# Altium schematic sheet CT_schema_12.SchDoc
size 742 x 377 mm
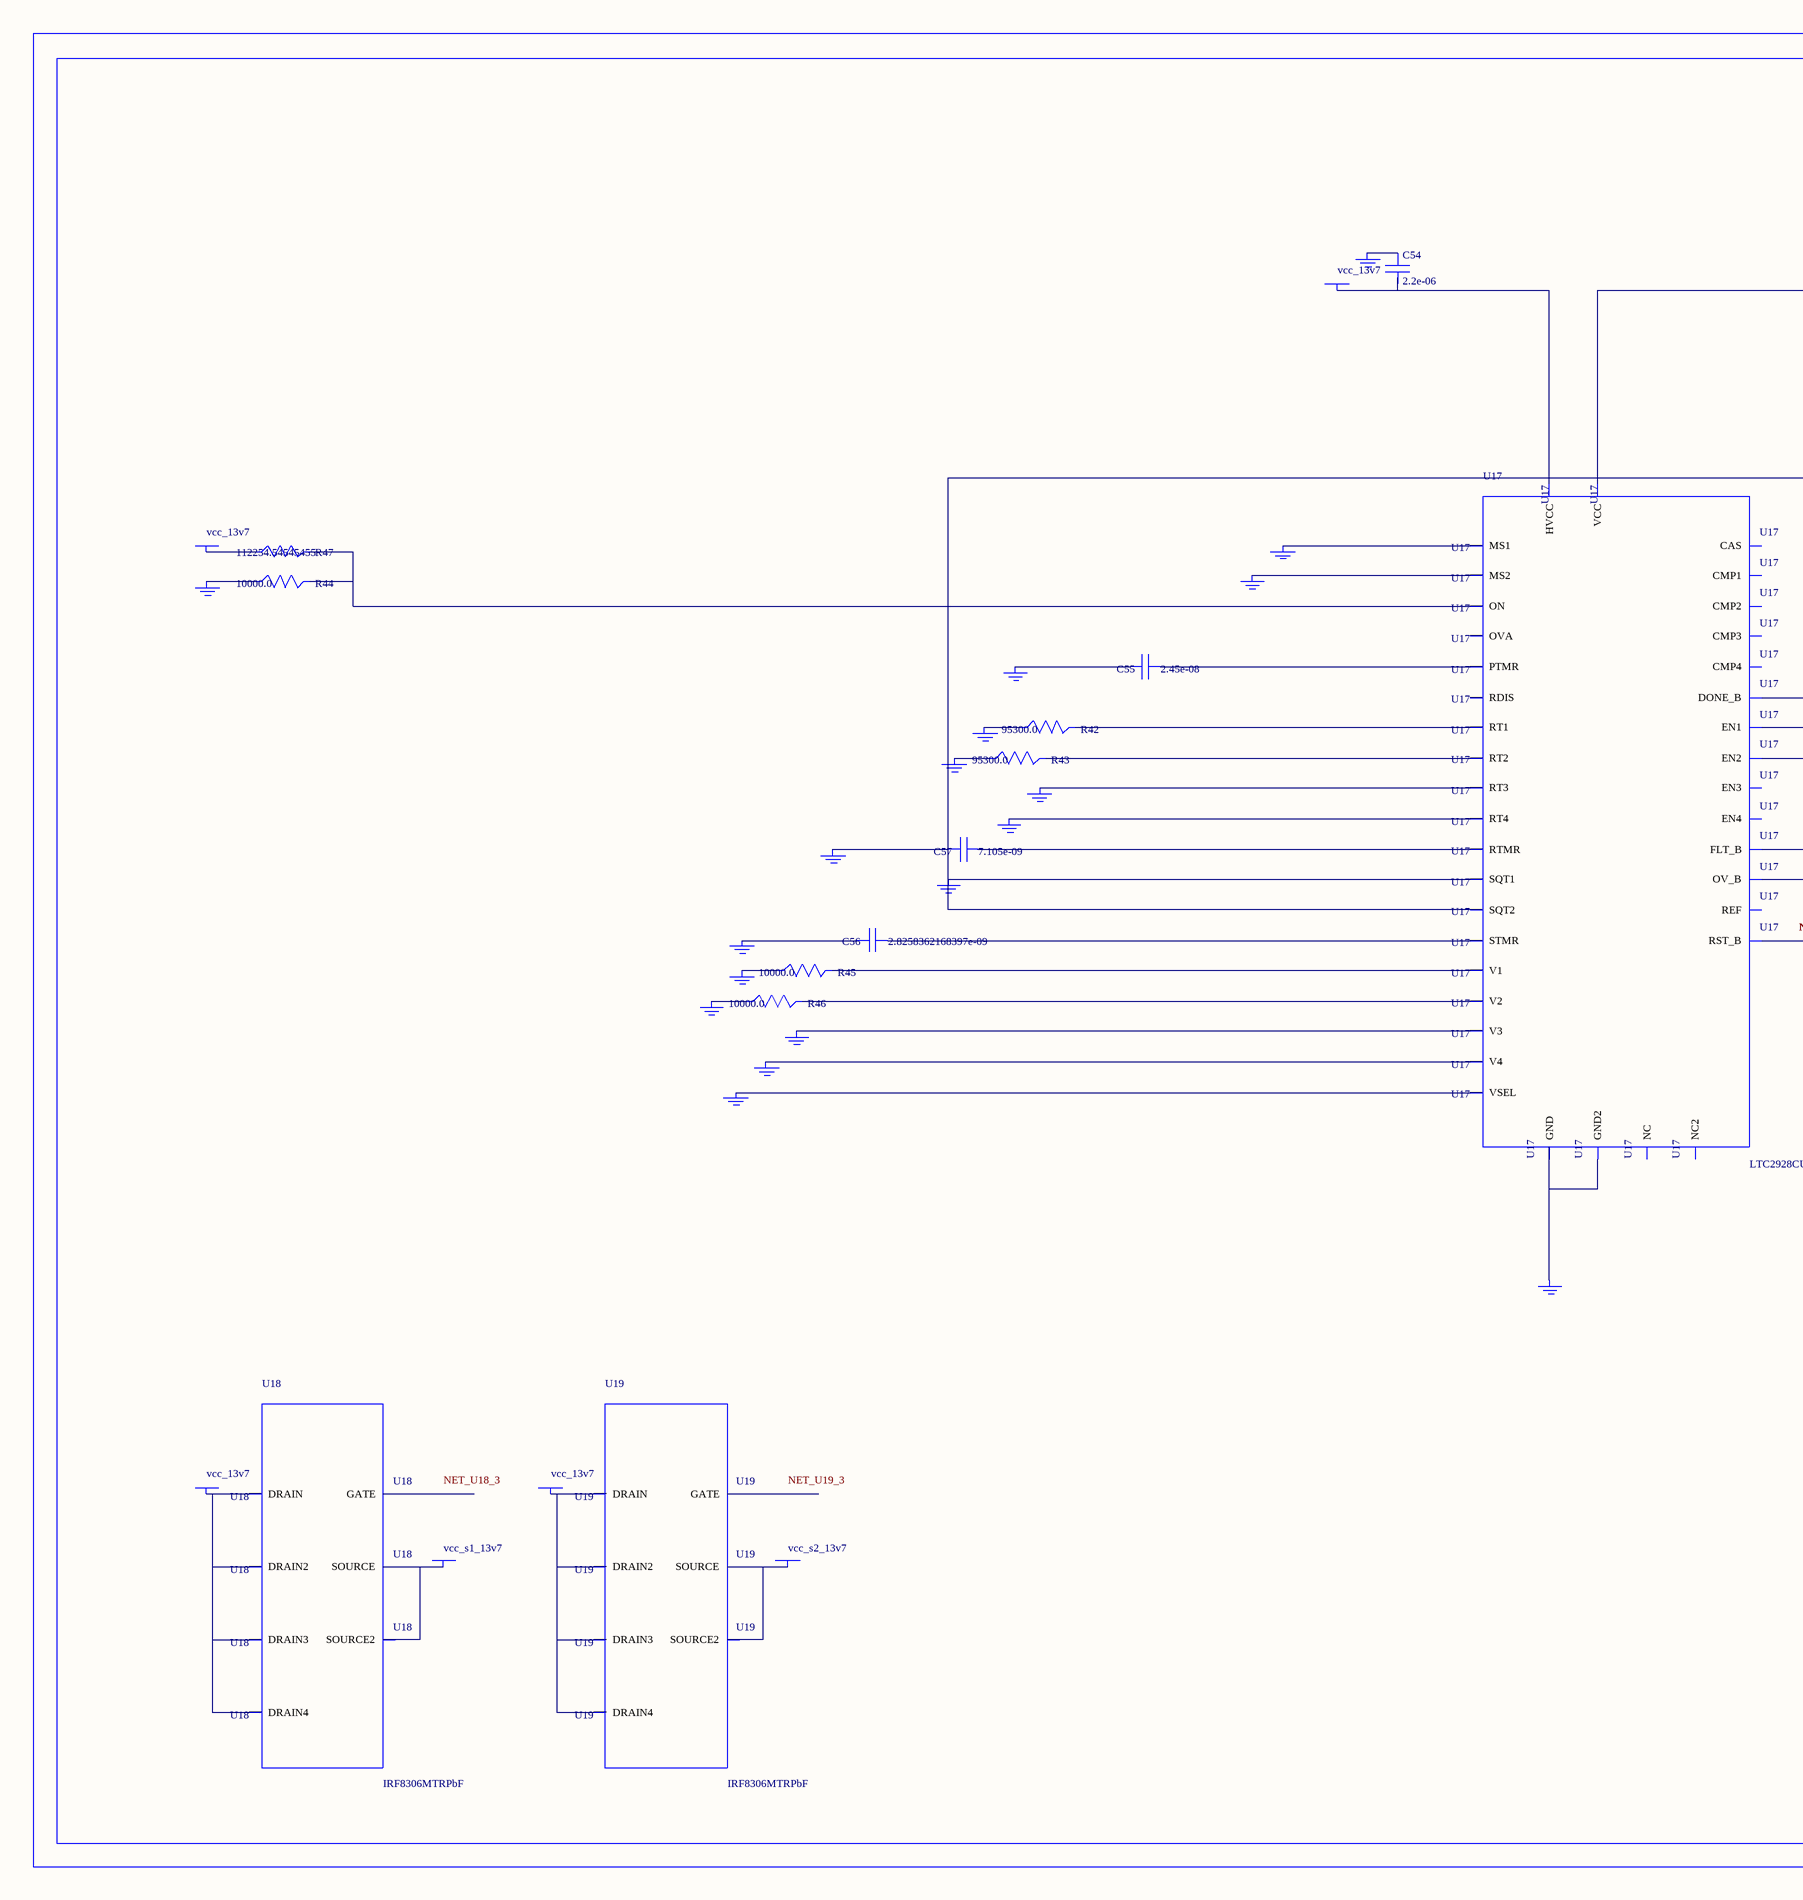
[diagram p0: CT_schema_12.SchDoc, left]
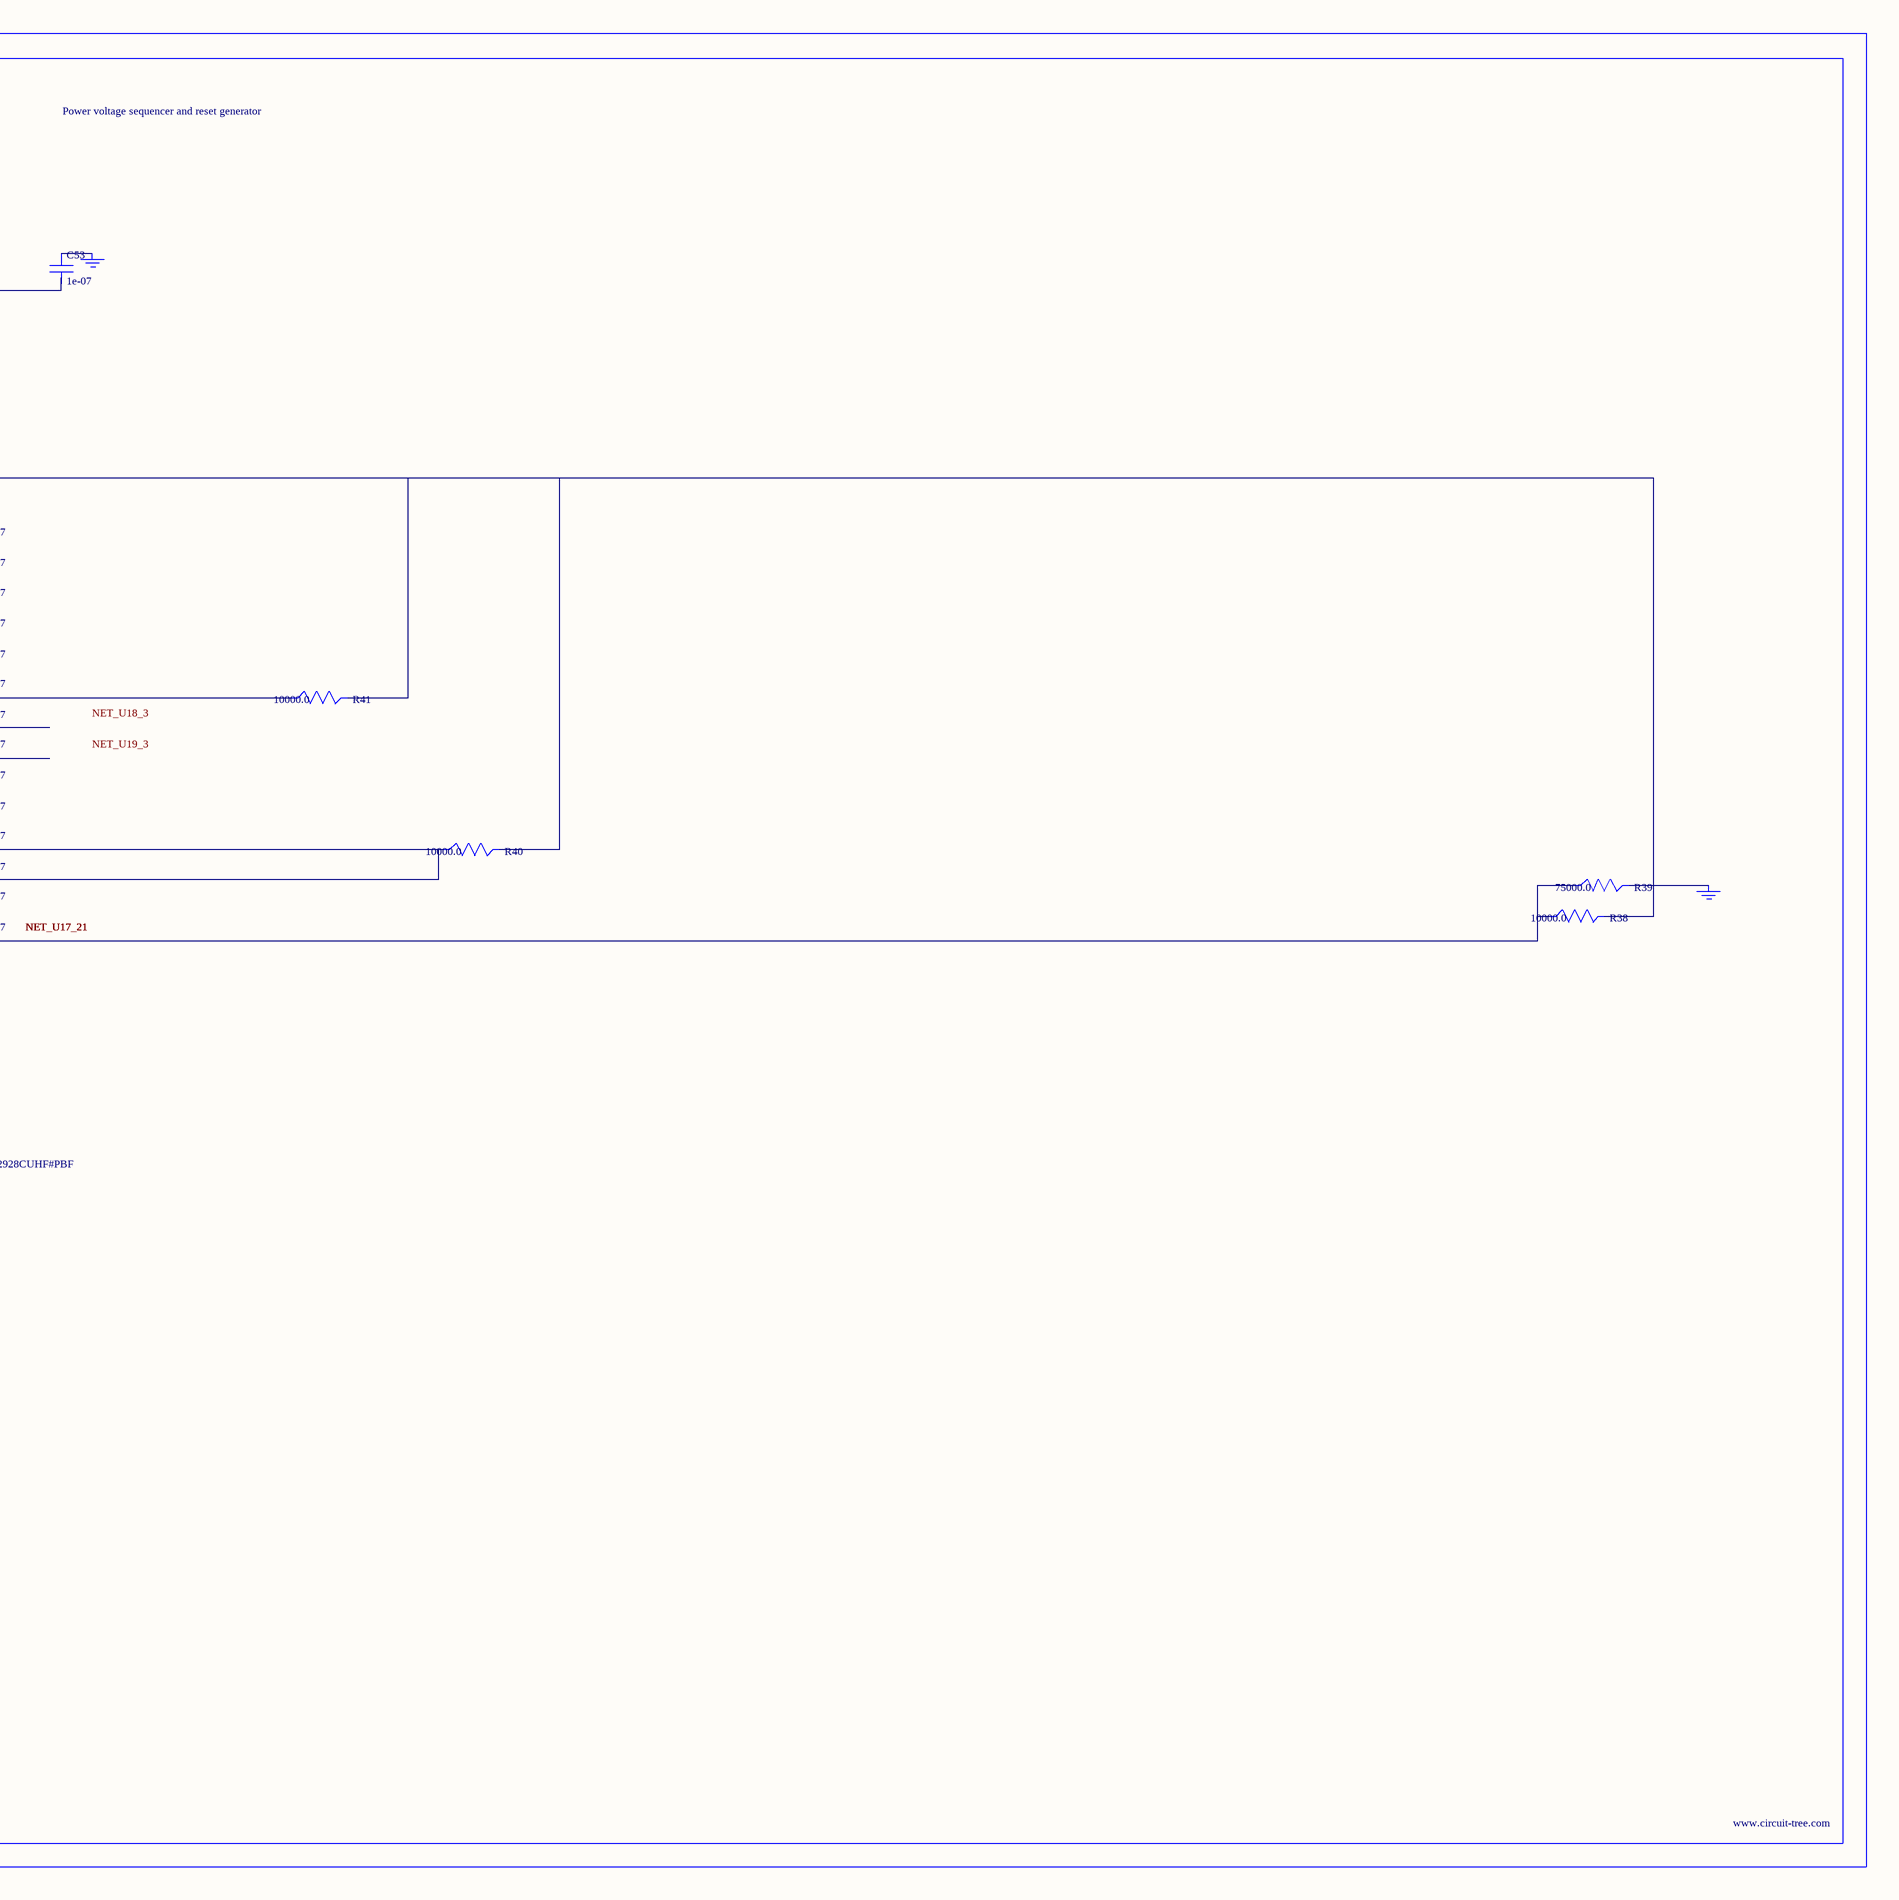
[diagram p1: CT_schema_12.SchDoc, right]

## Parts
BORDER11  (no value)
C53  1e-07  [C0402]
C54  2.2e-06  [C0603]
C55  2.45e-08  [R0603]
C56  2.8258362168397e-09  [R0603]
C57  7.105e-09  [R0603]
GND_INSTANCE_11_0  (no value)
GND_INSTANCE_11_1  (no value)
GND_INSTANCE_11_2  (no value)
GND_INSTANCE_11_3  (no value)
GND_INSTANCE_11_4  (no value)
GND_INSTANCE_11_5  (no value)
GND_INSTANCE_11_6  (no value)
GND_INSTANCE_11_7  (no value)
GND_INSTANCE_11_8  (no value)
GND_INSTANCE_11_9  (no value)
GND_INSTANCE_11_10  (no value)
GND_INSTANCE_11_11  (no value)
GND_INSTANCE_11_12  (no value)
GND_INSTANCE_11_13  (no value)
GND_INSTANCE_11_14  (no value)
GND_INSTANCE_11_15  (no value)
GND_INSTANCE_11_16  (no value)
GND_INSTANCE_11_17  (no value)
GND_INSTANCE_11_18  (no value)
GND_INSTANCE_11_19  (no value)
POWER_INSTANCE_11_0  vcc_13v7
POWER_INSTANCE_11_1  vcc_13v7
POWER_INSTANCE_11_2  vcc_13v7
POWER_INSTANCE_11_3  vcc_s1_13v7
POWER_INSTANCE_11_4  vcc_13v7
POWER_INSTANCE_11_5  vcc_s2_13v7
R38  10000.0  [R0603]
R39  75000.0  [R0603]
R40  10000.0  [R0603]
R41  10000.0  [R0603]
R42  95300.0  [R0603]
R43  95300.0  [R0603]
R44  10000.0  [R0603]
R45  10000.0  [R0603]
R46  10000.0  [R0603]
R47  112254.54545455  [R0603]
U17  LTC2928CUHF#PBF  [QFN-38_UHF]
U18  IRF8306MTRPbF  [IRF8306MTRPBF]
U19  IRF8306MTRPbF  [IRF8306MTRPBF]

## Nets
NetC53_1: C53.1 GND_INSTANCE_11_10.0(GND)
NetC53_2: C53.2 C57.2 GND_INSTANCE_11_5.0(GND) GND_INSTANCE_11_15.0(GND) R38.2 R40.2 R41.2 U17.10(SQT1) U17.11(SQT2) U17.22(VCC)
NetC54_1: C54.1 GND_INSTANCE_11_11.0(GND)
NetC54_2: C54.2 POWER_INSTANCE_11_1.0(PWR) U17.23(HVCC)
NetC55_1: C55.1 U17.27(PTMR)
NetC55_2: C55.2 GND_INSTANCE_11_14.0(GND)
NetC56_1: C56.1 U17.26(STMR)
NetC56_2: C56.2 GND_INSTANCE_11_13.0(GND)
NetC57_1: C57.1 U17.28(RTMR)
NetGND_INSTANCE_11_0_0: GND_INSTANCE_11_0.0(GND) R45.1
NetGND_INSTANCE_11_1_0: GND_INSTANCE_11_1.0(GND) R42.1
NetGND_INSTANCE_11_2_0: GND_INSTANCE_11_2.0(GND) R43.1
NetGND_INSTANCE_11_3_0: GND_INSTANCE_11_3.0(GND) U17.8(RT3)
NetGND_INSTANCE_11_4_0: GND_INSTANCE_11_4.0(GND) U17.9(RT4)
NetGND_INSTANCE_11_6_0: GND_INSTANCE_11_6.0(GND) U17.12(MS1)
NetGND_INSTANCE_11_7_0: GND_INSTANCE_11_7.0(GND) U17.13(MS2)
NetGND_INSTANCE_11_8_0: GND_INSTANCE_11_8.0(GND) R44.1
NetGND_INSTANCE_11_9_0: GND_INSTANCE_11_9.0(GND) R39.2
NetGND_INSTANCE_11_12_0: GND_INSTANCE_11_12.0(GND) U17.25(VSEL)
NetGND_INSTANCE_11_16_0: GND_INSTANCE_11_16.0(GND) U17.30(V4)
NetGND_INSTANCE_11_17_0: GND_INSTANCE_11_17.0(GND) U17.32(V3)
NetGND_INSTANCE_11_18_0: GND_INSTANCE_11_18.0(GND) R46.1
NetGND_INSTANCE_11_19_0: GND_INSTANCE_11_19.0(GND) U17.24(GND) U17.39(GND2)
NetPOWER_INSTANCE_11_0_0: POWER_INSTANCE_11_0.0(PWR) R47.1
NetPOWER_INSTANCE_11_2_0: POWER_INSTANCE_11_2.0(PWR) U18.1(DRAIN) U18.2(DRAIN2) U18.6(DRAIN3) U18.7(DRAIN4)
NetPOWER_INSTANCE_11_3_0: POWER_INSTANCE_11_3.0(PWR) U18.4(SOURCE) U18.5(SOURCE2)
NetPOWER_INSTANCE_11_4_0: POWER_INSTANCE_11_4.0(PWR) U19.1(DRAIN) U19.2(DRAIN2) U19.6(DRAIN3) U19.7(DRAIN4)
NetPOWER_INSTANCE_11_5_0: POWER_INSTANCE_11_5.0(PWR) U19.4(SOURCE) U19.5(SOURCE2)
NetR38_1: R38.1 R39.1 U17.21(RST_B)
NetR40_1: R40.1 U17.19(FLT_B) U17.20(OV_B)
NetR41_1: R41.1 U17.18(DONE_B)
NetR42_2: R42.2 U17.6(RT1)
NetR43_2: R43.2 U17.7(RT2)
NetR44_2: R44.2 R47.2 U17.16(ON)
NetR45_2: R45.2 U17.3(V1)
NetR46_2: R46.2 U17.38(V2)

Not connected (* = marked no-connect by the designer): U17 1(OVA) 2(EN1) 4(NC) 5(REF) 14(RDIS) 15(CAS) 17(NC2) 29(EN4) 31(EN3) 33(CMP3) 34(CMP4) 35(CMP1) 36(CMP2) 37(EN2); U18 3(GATE); U19 3(GATE)

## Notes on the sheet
- Labels drawn without touching a wire or pin: NET_U18_3, NET_U19_3

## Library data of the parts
BORDER11 = BORDER_PAGE11
C53 = C0402C104K3RACTU
C54 = GRM188R61H225KE1115D
C55 = C55
C56 = C56
C57 = C57
GND_INSTANCE_11_0-GND_INSTANCE_11_19 = GND
POWER_INSTANCE_11_0-POWER_INSTANCE_11_5 = PWR
R38 R40 R41 R44-R46 = RC0603JR-0710KL
R39 = RC0603JR-0775KL
R42 R43 = RC0603FR-0795K3L
R47 = R47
